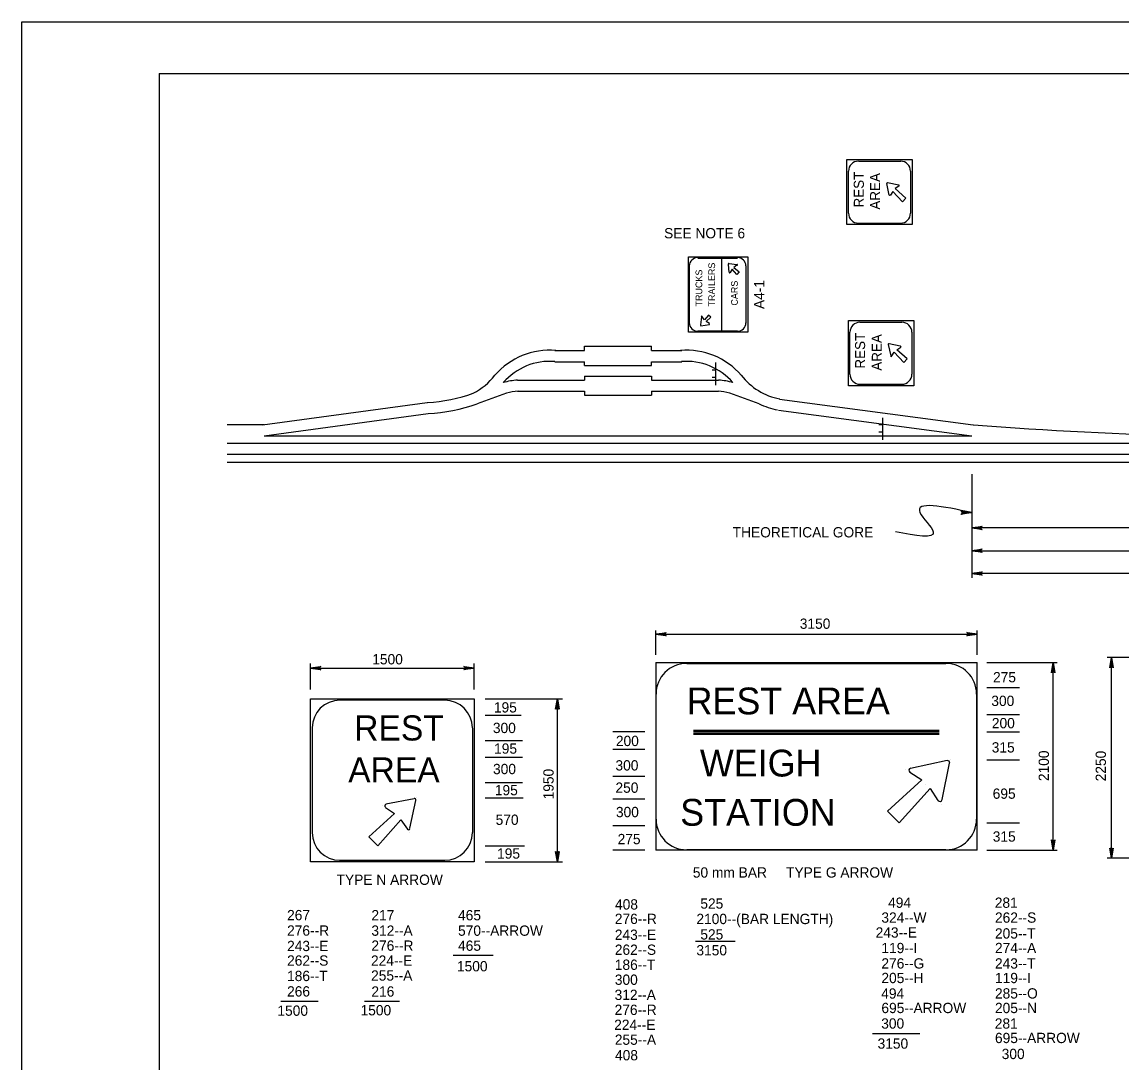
# Model space of a CAD drawing. Extents: x 649604 to 650509, y 298458 to 299646.
# Drawn here: x 649604.3 to 649924.8, y 299342.2 to 299645.6 of the extents above; entities that cross this region are included whole.
import ezdxf

# ---------------------------------------------------------------- set-up
doc = ezdxf.new("R2010")
doc.units = 0
for name, color, linetype in [('1', 7, 'Continuous'), ('2', 7, 'Continuous'), ('3', 7, 'Continuous'), ('PLT-BNDY', 7, 'Continuous')]:
    doc.layers.add(name, color=color, linetype=linetype)

# ---------------------------------------------------------------- blocks, each defined once
blk = doc.blocks.new('RARROW')
at = {"layer": '3'}
blk.add_lwpolyline([(-2.2695, 0.285), (-2.184875, 0.12075), (0, 0), (-2.2695, 0.285), (-2.38575, 0.384625), (0, 0), (-2.183125, -0.108), (-2.262875, -0.2705), (0, 0), (-2.38575, -0.379125), (-2.262875, -0.2705)], dxfattribs=at)

msp = doc.modelspace()

# ---------------------------------------------------------------- linework, layer by layer
at = {"layer": '1'}
for q in [(650430.31, 299630.63), (649644.31, 299066.63)]:
    msp.add_line((649644.31, 299630.63), q, dxfattribs=at)
at = {"layer": '2'}
for p, q in [((649848.31, 299605), (649860.56, 299605)), ((649856.56, 299598.75), (649856.56, 299598.75)), ((649857.19, 299595.13), (649856.56, 299598.5)), ((649856.69, 299598.75), (649860.06, 299598.13)), ((649860.06, 299597.75), (649858.94, 299597)), ((649858.31, 299596.13), (649857.56, 299595.13)), ((649861.06, 299593.13), (649858.31, 299596.13)), ((649858.31, 299596.13), (649858.31, 299596.13)), ((649858.94, 299597), (649858.94, 299597)), ((649858.94, 299597), (649862.06, 299594.25)), ((649862.06, 299594.25), (649861.06, 299593.13)), ((649863.94, 299586.5), (649844.81, 299586.5)), ((649860.56, 299586.88), (649848.31, 299586.88)), ((649801.44, 299576.75), (649812.94, 299576.75)), ((649808.44, 299555.5), (649808.44, 299576.75)), ((649810.56, 299575.13), (649812.81, 299574.88)), ((649810.56, 299575), (649810.56, 299575)), ((649810.56, 299572.63), (649810.31, 299574.88)), ((649810.69, 299572.63), (649810.69, 299572.63)), ((649810.69, 299572.38), (649810.69, 299572.38)), ((649810.69, 299572.38), (649810.69, 299572.38)), ((649811.44, 299573.5), (649810.81, 299572.5)), ((649812.81, 299572), (649811.44, 299573.5)), ((649811.44, 299573.5), (649811.44, 299573.5)), ((649811.69, 299573.75), (649811.69, 299573.75)), ((649812.81, 299574.63), (649811.94, 299574)), ((649811.94, 299574), (649811.94, 299574)), ((649811.94, 299574), (649813.44, 299572.75)), ((649812.81, 299574.63), (649812.81, 299574.63)), ((649813.44, 299572.75), (649812.81, 299572)), ((649812.81, 299572), (649812.81, 299572)), ((649812.94, 299574.63), (649812.94, 299574.63)), ((649812.94, 299574.63), (649812.94, 299574.63)), ((649813.44, 299572.75), (649813.44, 299572.75)), ((649802.44, 299559.63), (649802.19, 299557.25)), ((649802.56, 299559.88), (649802.56, 299559.88)), ((649803.31, 299558.75), (649802.69, 299559.63)), ((649804.56, 299560.13), (649803.31, 299558.75)), ((649803.81, 299558.25), (649805.19, 299559.5)), ((649805.19, 299559.5), (649804.56, 299560.13)), ((649802.19, 299557.13), (649802.19, 299557.13)), ((649802.31, 299557), (649804.81, 299557.38)), ((649803.81, 299558.25), (649803.81, 299558.25)), ((649804.81, 299557.63), (649803.81, 299558.25)), ((649804.81, 299557.5), (649804.81, 299557.5)), ((649804.81, 299557.5), (649804.81, 299557.5)), ((649848.69, 299558), (649860.94, 299558)), ((649800.94, 299555.13), (649799.31, 299555.13)), ((649801.44, 299555.5), (649812.94, 299555.5)), ((649808.81, 299555.13), (649807.81, 299555.13)), ((649759.69, 299549.75), (649768.31, 299549.75)), ((649768.31, 299551), (649787.94, 299551)), ((649768.31, 299549.75), (649768.31, 299551)), ((649787.94, 299549.75), (649787.94, 299551)), ((649787.94, 299549.75), (649796.69, 299549.75)), ((649856.81, 299551.75), (649856.81, 299551.75)), ((649856.94, 299551.5), (649857.69, 299548.25)), ((649860.44, 299551), (649857.19, 299551.75)), ((649859.44, 299550), (649860.56, 299550.75)), ((649862.44, 299547.38), (649859.44, 299550)), ((649859.44, 299550), (649859.44, 299550)), ((649860.94, 299551), (649860.94, 299551)), ((649759.69, 299546.5), (649768.31, 299546.5)), ((649768.31, 299545.38), (649768.31, 299546.5)), ((649787.94, 299545.38), (649787.94, 299546.5)), ((649787.94, 299546.5), (649796.69, 299546.5)), ((649806.69, 299539.63), (649806.69, 299546.25)), ((649857.81, 299547.75), (649857.81, 299547.75)), ((649857.94, 299548.25), (649858.69, 299549.25)), ((649858.69, 299549.25), (649858.69, 299549.25)), ((649858.69, 299549.25), (649861.44, 299546.25)), ((649861.44, 299546.25), (649862.44, 299547.38)), ((649768.31, 299545.38), (649787.94, 299545.38)), ((649806.69, 299544), (649805.56, 299544)), ((649748.81, 299541.13), (649768.31, 299541.13)), ((649768.31, 299542.25), (649787.94, 299542.25)), ((649768.31, 299542.25), (649768.31, 299541.13)), ((649787.94, 299542.25), (649787.94, 299541.13)), ((649787.94, 299541.13), (649807.44, 299541.13)), ((649806.69, 299541.88), (649805.56, 299541.88)), ((649860.94, 299539.88), (649848.69, 299539.88)), ((649748.81, 299537.88), (649768.31, 299537.88)), ((649768.31, 299537.88), (649768.31, 299536.75)), ((649768.31, 299536.75), (649787.94, 299536.75)), ((649787.94, 299537.88), (649787.94, 299536.75)), ((649787.94, 299537.88), (649807.44, 299537.88)), ((649864.44, 299539.5), (649845.31, 299539.5)), ((649674.44, 299528.13), (649722.44, 299534.63)), ((649825.19, 299535.63), (649881.69, 299528.13)), ((649674.94, 299524.88), (649722.81, 299531.38)), ((649722.81, 299531.38), (649722.81, 299531.38)), ((649722.81, 299531.38), (649722.81, 299531.38)), ((649824.94, 299532.38), (649824.94, 299532.38)), ((649824.94, 299532.38), (649881.31, 299524.88)), ((649855.31, 299523.75), (649855.31, 299530.13)), ((649674.94, 299528.13), (649664.19, 299528.13)), ((649855.31, 299528.13), (649854.19, 299528.13)), ((649674.94, 299524.88), (649881.31, 299524.88)), ((649674.94, 299524.88), (649674.94, 299524.88)), ((649674.94, 299524.88), (649674.94, 299524.88)), ((649855.31, 299526), (649854.19, 299526)), ((649664.19, 299522.75), (650390.69, 299522.75)), ((649664.19, 299519.5), (650390.69, 299519.5)), ((649664.19, 299517.25), (650390.69, 299517.25)), ((649881.31, 299513.75), (649881.31, 299483.5)), ((650085.69, 299498), (649881.31, 299498)), ((649881.31, 299491.38), (650176.94, 299491.38)), ((650311.69, 299484.75), (649881.31, 299484.75)), ((649789.13, 299460.96), (649789.13, 299468.13)), ((649789.13, 299467), (649882.88, 299467)), ((649882.88, 299460.96), (649882.88, 299468.13)), ((649930.04, 299460.25), (649920.81, 299460.25)), ((649922.06, 299401.63), (649922.06, 299460.25)), ((649688.44, 299450.9), (649688.44, 299458.5)), ((649688.44, 299457.13), (649736.19, 299457.13)), ((649736.19, 299450.9), (649736.19, 299458.5)), ((649789.13, 299458.75), (649882.88, 299458.75)), ((649789.13, 299458.75), (649789.13, 299404)), ((649798.15, 299458.49), (649873.75, 299458.49)), ((649882.88, 299404), (649882.88, 299458.75)), ((649885.67, 299458.75), (649906.17, 299458.75)), ((649905.05, 299404), (649905.05, 299458.75)), ((649885.67, 299451.5), (649895.21, 299451.5)), ((649688.44, 299400.63), (649688.44, 299448.13)), ((649739.4, 299448.13), (649761.94, 299448.13)), ((649760.44, 299400.63), (649760.44, 299448.13)), ((649789.21, 299413.06), (649789.21, 299449.55)), ((649882.7, 299449.55), (649882.7, 299413.06)), ((649885.67, 299443.63), (649895.21, 299443.63)), ((649739.4, 299443.38), (649749.93, 299443.38)), ((649688.94, 299439.63), (649688.94, 299409.13)), ((649735.81, 299409.13), (649735.81, 299439.63)), ((649785.95, 299438.5), (649776.63, 299438.5)), ((649800.13, 299439), (649871.76, 299439)), ((649800.13, 299438.88), (649871.76, 299438.88)), ((649800.13, 299438.5), (649871.76, 299438.5)), ((649800.13, 299438), (649871.76, 299438)), ((649800.13, 299437.88), (649871.76, 299437.88)), ((649885.67, 299438.5), (649895.21, 299438.5)), ((649739.4, 299436), (649750.28, 299436)), ((649739.4, 299431.13), (649750.28, 299431.13)), ((649785.95, 299433.38), (649776.63, 299433.38)), ((649862.01, 299427.63), (649862.01, 299427.63)), ((649874.13, 299430.13), (649863.38, 299427.88)), ((649874.13, 299430.13), (649863.38, 299427.88)), ((649872.63, 299418.75), (649874.76, 299429.38)), ((649872.63, 299418.75), (649874.76, 299429.38)), ((649875.01, 299430.38), (649875.01, 299430.38)), ((649885.67, 299430.38), (649895.21, 299430.38)), ((649785.95, 299425.5), (649776.63, 299425.5)), ((649866.76, 299424.5), (649856.76, 299415.38)), ((649866.76, 299424.5), (649856.76, 299415.38)), ((649863.26, 299426.75), (649866.76, 299424.5)), ((649863.26, 299426.75), (649866.76, 299424.5)), ((649866.76, 299424.5), (649866.76, 299424.5)), ((649739.4, 299423.75), (649750.28, 299423.75)), ((649860.13, 299412), (649869.13, 299422)), ((649860.13, 299412), (649869.13, 299422)), ((649867.88, 299423.25), (649867.88, 299423.25)), ((649869.13, 299422), (649871.38, 299418.5)), ((649869.13, 299422), (649869.13, 299422)), ((649869.13, 299422), (649871.38, 299418.5)), ((649718.69, 299419), (649710.44, 299417.38)), ((649717.44, 299410.38), (649719.19, 299418.5)), ((649719.31, 299419.25), (649719.31, 299419.25)), ((649739.4, 299419.25), (649750.51, 299419.25)), ((649785.95, 299418.88), (649776.63, 299418.88)), ((649712.94, 299414.75), (649705.44, 299407.88)), ((649709.31, 299417.13), (649709.31, 299417.13)), ((649710.31, 299416.5), (649712.94, 299414.75)), ((649712.94, 299414.75), (649712.94, 299414.75)), ((649856.76, 299415.38), (649860.13, 299412)), ((649856.76, 299415.38), (649856.76, 299415.38)), ((649856.76, 299415.38), (649860.13, 299412)), ((649872.38, 299417.25), (649872.38, 299417.25)), ((649708.06, 299405.25), (649714.81, 299412.88)), ((649714.81, 299412.88), (649714.81, 299412.88)), ((649714.81, 299412.88), (649716.69, 299410.13)), ((649860.13, 299412), (649860.13, 299412)), ((649885.67, 299412), (649895.21, 299412)), ((649717.19, 299409.25), (649717.19, 299409.25)), ((649785.95, 299411.13), (649776.63, 299411.13)), ((649705.44, 299407.88), (649708.06, 299405.25)), ((649739.4, 299405.25), (649750.85, 299405.25)), ((649785.95, 299404), (649776.63, 299404)), ((649882.88, 299404), (649789.13, 299404)), ((649873.75, 299404.12), (649798.15, 299404.12)), ((649885.67, 299404), (649906.17, 299404)), ((649739.4, 299400.63), (649761.94, 299400.63)), ((649930.04, 299401.63), (649920.81, 299401.63)), ((649800.7, 299377.45), (649812.29, 299377.45)), ((649730.06, 299373.34), (649741.69, 299373.34)), ((649679.81, 299359.97), (649690.69, 299359.97)), ((649704.19, 299359.97), (649714.44, 299359.97)), ((649852.31, 299350.5), (649866.19, 299350.5))]:
    msp.add_line(p, q, dxfattribs=at)
for points in [[(649844.81, 299586.5), (649844.81, 299605.5), (649846.81, 299605.5), (649849.81, 299605.5), (649851.69, 299605.5), (649854.56, 299605.5), (649856.56, 299605.5), (649862.19, 299605.5), (649863.94, 299605.5), (649863.94, 299605.5), (649863.94, 299586.5), (649863.94, 299586.5)], [(649845.31, 299589.88), (649845.31, 299602.13)], [(649863.44, 299602.13), (649863.44, 299589.88)], [(649798.69, 299555.13), (649798.69, 299577.13), (649800.31, 299577.13), (649802.19, 299577.13), (649803.69, 299577.13), (649805.69, 299577.13), (649807.06, 299577.13), (649808.56, 299577.13), (649811.81, 299577.13), (649815.94, 299577.13), (649815.94, 299555.13), (649811.19, 299555.13), (649809.31, 299555.13), (649807.06, 299555.13), (649804.69, 299555.13), (649801.44, 299555.13), (649798.69, 299555.13)], [(649798.94, 299557.75), (649798.94, 299574.5)], [(649815.44, 299574.5), (649815.44, 299557.75)], [(649845.31, 299539.5), (649845.31, 299558.5), (649847.31, 299558.5), (649850.19, 299558.5), (649852.06, 299558.5), (649855.06, 299558.5), (649856.81, 299558.5), (649862.56, 299558.5), (649864.44, 299558.5), (649864.44, 299558.5), (649864.44, 299539.5), (649864.44, 299539.5)], [(649845.69, 299542.88), (649845.69, 299555.13)], [(649863.81, 299555.13), (649863.81, 299542.88)], [(649688.44, 299448.13), (649736.19, 299448.13), (649736.19, 299443.38), (649736.19, 299436), (649736.19, 299431.13), (649736.19, 299423.75), (649736.19, 299419.25), (649736.19, 299405.25), (649736.19, 299400.63), (649736.19, 299400.63), (649688.44, 299400.63), (649688.44, 299400.63)], [(649727.56, 299447.75), (649696.94, 299447.75)], [(649696.94, 299401.13), (649727.56, 299401.13)]]:
    msp.add_lwpolyline(points, dxfattribs=at)
for centre, radius, start, end in [((649848.27, 299602.08), 2.93, 90, 180), ((649860.49, 299602.08), 2.93, 0, 90), ((649856.7, 299598.54), 0.183, 78.0958, 191.9043), ((649856.7, 299598.54), 0.183, 78.0958, 191.9043), ((649859.98, 299597.85), 0.183, 302.692, 78.0958), ((649859.98, 299597.85), 0.183, 302.692, 78.0958), ((649857.39, 299595.26), 0.183, 191.9043, 327.308), ((649857.39, 299595.26), 0.183, 191.9042, 327.308), ((649848.27, 299589.86), 2.93, 180, 270), ((649860.49, 299589.86), 2.93, 270, 0), ((649801.36, 299574.44), 2.44, 90, 180), ((649810.44, 299575), 0.153, 84.0498, 185.9502), ((649812.99, 299574.44), 2.44, 0, 90), ((649810.69, 299572.6), 0.153, 185.9502, 328.4461), ((649812.84, 299574.75), 0.153, 301.5539, 84.0498), ((649802.55, 299559.61), 0.153, 31.5539, 174.0498), ((649801.36, 299557.82), 2.44, 180, 270), ((649802.3, 299557.22), 0.153, 174.0498, 275.9502), ((649804.69, 299557.47), 0.153, 275.9502, 58.4461), ((649812.99, 299557.82), 2.44, 270, 0), ((649848.69, 299555.09), 2.93, 90, 180), ((649860.91, 299555.09), 2.93, 0, 90), ((649758.25, 299528.67), 21.21, 85.4134, 139.1043), ((649798.05, 299528.67), 21.21, 40.8957, 94.5866), ((649857.12, 299551.56), 0.183, 78.0958, 191.9043), ((649857.12, 299551.56), 0.183, 78.0958, 191.9043), ((649860.4, 299550.87), 0.183, 302.692, 78.0958), ((649860.4, 299550.87), 0.183, 302.692, 78.0958), ((649758.25, 299528.67), 17.95, 85.4134, 139.1043), ((649798.05, 299528.67), 17.95, 40.8957, 94.5866), ((649857.81, 299548.27), 0.183, 191.9043, 327.308), ((649857.81, 299548.27), 0.183, 191.9043, 327.308), ((649848.69, 299542.87), 2.93, 180, 270), ((649860.91, 299542.87), 2.93, 270, 0), ((649727.53, 299553.9), 18.56, 296.8793, 322.3109), ((649749.74, 299523.33), 17.82, 92.9526, 106.4866), ((649806.56, 299523.33), 17.82, 73.5134, 87.0474), ((649828.77, 299553.9), 18.56, 217.6891, 259.2048), ((649719.77, 299582.56), 48.03, 273.3346, 289.6636), ((651988.02, 293192.03), 6729.85, 109.463364, 109.540836), ((649749.74, 299523.33), 14.56, 92.9526, 106.4866), ((649806.56, 299523.33), 14.56, 73.5134, 87.0474), ((647568.28, 293192.03), 6729.85, 70.459164, 70.536636), ((649719.77, 299582.56), 51.29, 273.3346, 289.6636), ((649828.77, 299553.9), 21.82, 244.1957, 259.2048), ((649975.83, 300763.06), 1238.57, 265.6447, 268.64351), ((649798.15, 299449.55), 8.94, 90, 180), ((649873.75, 299449.55), 8.94, 0, 90), ((649697.03, 299439.68), 8.08, 90, 180), ((649727.58, 299439.68), 8.08, 0, 90), ((649863.63, 299427.28), 0.659, 101.7398, 236.6838), ((649863.63, 299427.28), 0.659, 101.7398, 236.6838), ((649874.21, 299429.48), 0.659, 348.2602, 101.7398), ((649874.21, 299429.48), 0.659, 348.2602, 101.7398), ((649718.74, 299418.62), 0.458, 348.0958, 101.9043), ((649718.74, 299418.62), 0.458, 348.0958, 101.9043), ((649872.01, 299418.9), 0.659, 213.3162, 348.2602), ((649872.01, 299418.9), 0.659, 213.3162, 348.2602), ((649710.53, 299416.89), 0.458, 101.9043, 237.308), ((649710.53, 299416.89), 0.458, 101.9043, 237.308), ((649798.15, 299413.06), 8.94, 180, 270), ((649873.75, 299413.06), 8.94, 270, 0), ((649697.03, 299409.13), 8.08, 180, 270), ((649717.01, 299410.41), 0.458, 212.692, 348.0958), ((649717.01, 299410.41), 0.458, 212.692, 348.0957), ((649727.58, 299409.13), 8.08, 270, 0)]:
    msp.add_arc(centre, radius, start, end, dxfattribs=at)
msp.add_spline([(649881.31, 299502.5), (649866.19, 299502.5), (649870.06, 299496.88), (649859.06, 299496.88)], degree=3, dxfattribs=at)
at = {"layer": 'PLT-BNDY'}
msp.add_lwpolyline([(649604.31, 299645.63), (650445.31, 299645.63), (650445.31, 299051.63), (649604.31, 299051.63)], close=True, dxfattribs=at)

# ---------------------------------------------------------------- block references
at = {"layer": '2', "xscale": 1.2574347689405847, "yscale": 1.3092961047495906}
for p in [(649881.17, 299502.48), (649882.88, 299467), (649736.19, 299457.13)]:
    msp.add_blockref('RARROW', p, dxfattribs=at)
for p, rotation in [((649881.31, 299498), 180), ((649881.31, 299491.38), 180), ((649881.31, 299484.75), 180), ((649789.13, 299467), 180), ((649922.06, 299460.25), 89.99999999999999), ((649688.44, 299457.13), 180), ((649905.05, 299458.75), 89.99999999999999), ((649760.44, 299448.13), 89.99999999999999), ((649905.05, 299404), -90.00000000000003), ((649760.44, 299400.63), -90.00000000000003), ((649922.06, 299401.63), -90.00000000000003)]:
    msp.add_blockref('RARROW', p, dxfattribs=dict(at, rotation=rotation))

# ---------------------------------------------------------------- texts
at = {"layer": '2'}
for s, height, p in [('REST', 2.932, (649849.81, 299591.5)), ('AREA', 2.932, (649854.56, 299590.88)), ('TRAILERS', 1.955, (649806.44, 299562.63)), ('TRUCKS', 1.955, (649802.69, 299562.63)), ('CARS', 1.955, (649813.06, 299562.88)), ('A4-1', 3, (649820.81, 299561.88)), ('REST', 2.932, (649850.19, 299544.5)), ('AREA', 2.932, (649855.06, 299543.88)), ('2100', 3, (649903.79, 299424.16)), ('2250', 3, (649920.41, 299424.09)), ('1950', 3, (649759.35, 299418.82))]:
    msp.add_text(s, height=height, rotation=90, dxfattribs=at).set_placement(p)
for s, height, p in [('SEE NOTE 6', 3, (649791.56, 299582.5)), ('THEORETICAL GORE', 3, (649811.56, 299495.25)), ('3150', 3, (649831.13, 299468.58)), ('1500', 3, (649706.46, 299458.21)), ('275', 3, (649887.49, 299452.97)), ('REST AREA', 7.82, (649798.13, 299443.63)), ('195', 3, (649741.93, 299444.17)), ('300', 3, (649886.99, 299446.07)), ('REST', 7.33, (649701.19, 299436)), ('300', 3, (649741.64, 299438.17)), ('200', 3, (649887.15, 299439.57)), ('200', 3, (649777.51, 299434.38)), ('195', 3, (649741.99, 299432.15)), ('315', 3, (649887.11, 299432.5)), ('AREA', 7.33, (649699.44, 299423.75)), ('WEIGH', 7.82, (649802.01, 299425.5)), ('300', 3, (649741.68, 299426.18)), ('300', 3, (649777.38, 299427.25)), ('195', 3, (649742.21, 299420.02)), ('250', 3, (649777.38, 299420.75)), ('695', 3, (649887.39, 299419)), ('STATION', 7.82, (649796.26, 299411.13)), ('300', 3, (649777.52, 299413.63)), ('570', 3, (649742.44, 299411.39)), ('275', 3, (649778.01, 299405.75)), ('315', 3, (649887.41, 299406.5)), ('195', 3, (649742.86, 299401.53)), ('50 mm BAR     TYPE G ARROW', 3, (649799.94, 299396)), ('TYPE N ARROW', 3, (649696.06, 299393.88)), (' 408   ', 3, (649776.14, 299386.69)), (' 525             ', 3, (649801.02, 299386.94)), ('494      ', 3, (649856.89, 299387.19)), (' 281       ', 3, (649886.89, 299387.19)), ('267   ', 3, (649681.62, 299383.56)), ('217   ', 3, (649706.21, 299383.53)), ('465       ', 3, (649731.48, 299383.53)), (' 324--W    ', 3, (649853.82, 299382.84)), (' 262--S    ', 3, (649886.94, 299382.84)), (' 276--R', 3, (649776.08, 299382.47)), ('2100--(BAR LENGTH)', 3, (649800.99, 299382.44)), ('276--R', 3, (649681.62, 299379.06)), ('312--A', 3, (649706.21, 299379.03)), ('570--ARROW', 3, (649731.48, 299379.03)), (' 243--E', 3, (649776.08, 299377.84)), (' 525             ', 3, (649801.02, 299377.94)), ('  243--E     ', 3, (649851.03, 299378.49)), (' 205--T    ', 3, (649886.94, 299378.22)), ('243--E', 3, (649681.62, 299374.56)), ('276--R', 3, (649706.21, 299374.66)), ('465       ', 3, (649731.48, 299374.65)), (' 262--S', 3, (649776.08, 299373.47)), ('3150             ', 3, (649800.99, 299373.31)), (' 119--I    ', 3, (649853.82, 299373.97)), (' 274--A    ', 3, (649886.94, 299373.97)), ('262--S', 3, (649681.62, 299370.31)), ('224--E', 3, (649706.09, 299370.28)), ('1500        ', 3, (649731.16, 299368.65)), (' 186--T', 3, (649776.08, 299369.09)), (' 276--G    ', 3, (649853.82, 299369.47)), (' 243--T    ', 3, (649886.94, 299369.47)), ('186--T', 3, (649681.62, 299365.81)), ('255--A', 3, (649706.12, 299365.94)), (' 300   ', 3, (649776.08, 299364.72)), (' 205--H    ', 3, (649853.82, 299365.22)), (' 119--I    ', 3, (649886.94, 299365.22)), ('266   ', 3, (649681.62, 299361.31)), ('216   ', 3, (649706.21, 299361.28)), (' 494       ', 3, (649853.77, 299360.69)), (' 285--O    ', 3, (649886.94, 299360.72)), (' 312--A', 3, (649776.02, 299360.31)), ('1500    ', 3, (649678.8, 299355.69)), ('1500    ', 3, (649703.05, 299355.81)), (' 276--R', 3, (649776.02, 299355.94)), (' 695--ARROW', 3, (649853.82, 299356.47)), (' 205--N    ', 3, (649886.94, 299356.47)), (' 224--E', 3, (649775.9, 299351.56)), (' 300       ', 3, (649853.77, 299351.94)), (' 281       ', 3, (649886.89, 299351.94)), (' 695--ARROW', 3, (649886.94, 299347.72)), (' 255--A', 3, (649776.08, 299347.22)), ('3150       ', 3, (649853.82, 299346.09)), (' 408   ', 3, (649776.14, 299342.69)), ('300      ', 3, (649890.02, 299343.06))]:
    msp.add_text(s, height=height, dxfattribs=at).set_placement(p)

doc.saveas('drawing.dxf')
